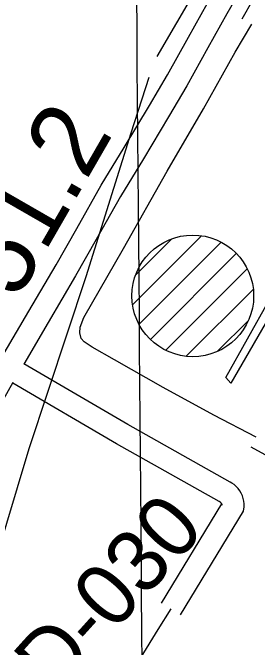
# Model space of a CAD drawing. Extents: x 3568792 to 3606828, y 529143 to 554785.
# Drawn here: x 3576112 to 3576440, y 543547 to 544399 of the extents above; entities that cross this region are included whole.
import ezdxf

# ---------------------------------------------------------------- set-up
doc = ezdxf.new("R2010")
doc.units = 0
for name, color, linetype in [('V-DOMW-TANK', 7, 'Continuous'), ('V-GRID-MAJR', 7, 'Continuous'), ('V-RIVR-RANG-IDEN', 7, 'Continuous'), ('V-ROAD-CNTR', 7, 'Continuous'), ('V-SURV-IDEN', 7, 'Continuous'), ('V-UTIL-LINE', 7, 'Continuous')]:
    doc.layers.add(name, color=color, linetype=linetype)

msp = doc.modelspace()

# ---------------------------------------------------------------- linework, layer by layer
at = {"layer": 'V-DOMW-TANK'}
for p, q in [((3576272.842558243, 544007.5763686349), (3576365.0033739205, 544099.738184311)), ((3576277.0155498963, 544047.104289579), (3576325.5394528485, 544095.629192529)), ((3576281.4705409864, 543980.848422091), (3576391.602320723, 544090.981201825)), ((3576296.6205106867, 543960.644462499), (3576411.8142802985, 544075.8372321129)), ((3576317.328469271, 543945.996491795), (3576426.4622510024, 544055.1302735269)), ((3576344.554414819, 543937.8675080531), (3576434.4282350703, 544027.741328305)), ((3576386.7273304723, 543944.6844944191), (3576428.1542476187, 543986.1124115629))]:
    msp.add_line(p, q, dxfattribs=at)
msp.add_circle((3576353.4593970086, 544019.025345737), 81.67426354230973, dxfattribs=at)
at = {"layer": 'V-GRID-MAJR'}
msp.add_spline([(3576358.556, 534575.836), (3576309.205, 540634.7170000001), (3576259.838, 546695.532), (3576210.471, 552756.361), (3576210.455, 552758.279)], degree=3, dxfattribs=at)
at = {"layer": 'V-ROAD-CNTR'}
for points in [[(3576419.71040469, 544391.2001050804), (3576434.587358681, 544417.3650241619), (3576491.7510152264, 544517.9048021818), (3576561.08299443, 544638.7284732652), (3576579.829603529, 544670.8934126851), (3576625.306205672, 544748.9143423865), (3576628.793597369, 544755.1861647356), (3576686.8636082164, 544859.6713216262), (3576727.8480226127, 544929.3169550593), (3576742.904226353, 544957.1363516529), (3576754.8414024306, 544977.2509142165)], [(3576424.323517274, 544441.4888622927), (3576399.3528909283, 544397.5691804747), (3576373.878315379, 544351.9035858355), (3576345.365161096, 544301.0615776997), (3576321.055014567, 544259.5075570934), (3576287.2952697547, 544203.0098993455), (3576256.6225102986, 544152.4297083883), (3576224.03693701, 544094.9068777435), (3576196.1905909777, 544045.7636735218), (3576159.49547521, 543983.2666941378), (3576126.6108397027, 543927.2482714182)], [(3576100.4052123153, 543941.8667665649), (3576133.6245247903, 543998.4553058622), (3576170.203409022, 544060.7543264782), (3576197.93506299, 544109.6951222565), (3576230.7394897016, 544167.6042916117), (3576261.5927302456, 544218.4821006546), (3576295.2309854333, 544274.7764429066), (3576319.332838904, 544315.9744223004), (3576347.6956846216, 544366.5484141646), (3576373.213109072, 544412.2908195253)], [(3576438.413, 543829.362), (3576381.63, 543858.91), (3576313.577, 543895.9990000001), (3576248.579, 543933.115), (3576218.3880000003, 543950.167), (3576207.632, 543957.204), (3576203.517, 543961.751), (3576201.924, 543969.373), (3576202.366, 543977.0160000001), (3576207.347, 543989.792), (3576260.517, 544082.427), (3576319.1920000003, 544186.314), (3576367.855, 544270.253), (3576410.4760000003, 544346.502), (3576432.75, 544383.786)], [(3576337.10654873, 543590.9102464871), (3576421.429517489, 543729.744322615), (3576422.221123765, 543735.802710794), (3576422.2941385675, 543739.5745486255), (3576421.9557295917, 543743.3076780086), (3576421.2158487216, 543746.9928880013), (3576420.072509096, 543750.5758263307), (3576418.5498868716, 543754.0097121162), (3576416.656254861, 543757.2617806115), (3576414.421676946, 543760.2837812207), (3576411.8722980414, 543763.0444248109), (3576409.0279548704, 543765.516527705), (3576405.939258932, 543767.6525356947), (3576403.470429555, 543768.9924162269), (3576266.282036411, 543846.2586733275), (3576126.9616032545, 543927.8457912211)], [(3576112.225000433, 543902.5328536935), (3576099.438073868, 543880.376757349), (3576065.1424564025, 543818.3639963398), (3576029.0736235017, 543755.1294667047), (3575996.0339548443, 543699.0717255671), (3575961.0609705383, 543637.7085627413), (3575938.839005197, 543599.7011187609), (3575915.0371579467, 543557.4462324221), (3575888.4770153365, 543510.1760155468), (3575871.57982207, 543474.8691709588), (3575869.695000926, 543471.0152397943), (3575855.2751701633, 543441.5495422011), (3575828.328829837, 543454.736457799), (3575842.7469990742, 543484.1987602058), (3575844.57417793, 543487.9348290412), (3575861.8409846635, 543524.0139844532), (3575888.8908420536, 543572.1557675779), (3575912.818994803, 543614.6348812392), (3575935.079029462, 543652.7074372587), (3575970.0780451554, 543714.1162744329), (3576003.1203764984, 543770.1785332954), (3576038.985543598, 543833.0560036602), (3576073.317926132, 543895.135242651), (3576085.79660246, 543916.7572292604)], [(3576311.4654512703, 543606.4837535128), (3576392.502482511, 543739.9076773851), (3576392.258876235, 543738.043289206), (3576392.2678614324, 543738.5074513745), (3576392.2242704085, 543738.9883219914), (3576392.1301512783, 543739.4571119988), (3576391.987490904, 543739.9041736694), (3576391.794113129, 543740.3402878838), (3576391.557745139, 543740.7462193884), (3576391.2723230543, 543741.1322187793), (3576390.949701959, 543741.4815751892), (3576390.6000451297, 543741.785472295), (3576390.206741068, 543742.0574643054), (3576388.953570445, 543742.7375837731), (3576251.3399635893, 543820.2433266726), (3576111.8701171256, 543901.917942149)], [(3576431.2625481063, 543816.1759832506), (3576473.8405651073, 543793.0869740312), (3576539.7115821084, 543757.366964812)], [(3576140.951, 543281.608), (3576169.273, 543330.508), (3576210.88, 543406.237), (3576258.0100000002, 543490.672), (3576307.214, 543571.049), (3576324.286, 543598.697)]]:
    msp.add_lwpolyline(points, dxfattribs=at)
at = {"layer": 'V-UTIL-LINE'}
for points in [[(3576305.512, 544340.545), (3576384.782, 544476.691), (3576487.216, 544642.575)], [(3576057.81, 543561.035), (3576134.022, 543814.276), (3576210.429, 544045.116), (3576270.872, 544238.132), (3576295.003, 544312.86)], [(3576465.162, 544006.979), (3576404.555, 543901.756), (3576397.725, 543909.502), (3576456.052, 544013.356)]]:
    msp.add_lwpolyline(points, dxfattribs=at)

# ---------------------------------------------------------------- texts
at = {"layer": 'V-RIVR-RANG-IDEN'}
msp.add_text('D-030', height=83, rotation=47.95832571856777, dxfattribs=at).set_placement((3576169.1530281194, 543479.9714623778))
at = {"layer": 'V-SURV-IDEN'}
msp.add_text('5355+51.2', height=100, rotation=60.06999470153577, dxfattribs=at).set_placement((3575930.225365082, 543686.3191717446))

doc.saveas('drawing.dxf')
